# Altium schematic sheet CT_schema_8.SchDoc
size 278 x 170 mm
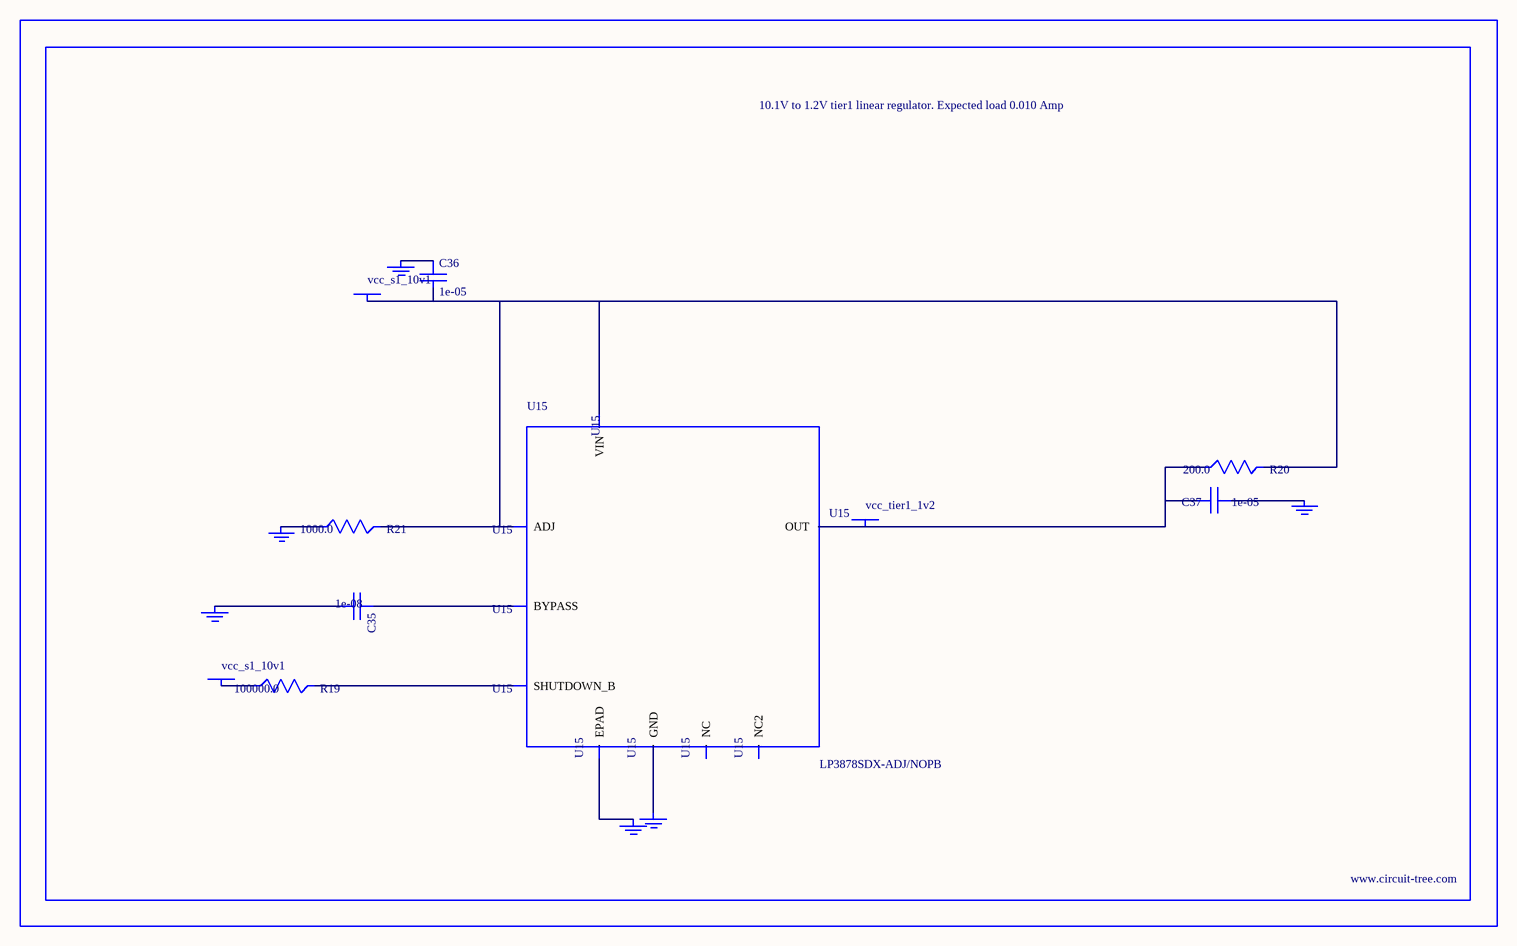
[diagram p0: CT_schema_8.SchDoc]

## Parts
BORDER7  (no value)
C35  1e-08  [C0402]
C36  1e-05  [C1206]
C37  1e-05  [C0805]
GND_INSTANCE_7_0  (no value)
GND_INSTANCE_7_1  (no value)
GND_INSTANCE_7_2  (no value)
GND_INSTANCE_7_3  (no value)
GND_INSTANCE_7_4  (no value)
GND_INSTANCE_7_5  (no value)
POWER_INSTANCE_7_0  vcc_s1_10v1
POWER_INSTANCE_7_1  vcc_s1_10v1
POWER_INSTANCE_7_2  vcc_tier1_1v2
R19  100000.0  [R0603]
R20  200.0  [R0603]
R21  1000.0  [R0603]
U15  LP3878SDX-ADJ/NOPB  [WSON-8]

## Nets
NetC35_1: C35.1 U15.1(BYPASS)
NetC35_2: C35.2 GND_INSTANCE_7_0.0(GND)
NetC36_1: C36.1 GND_INSTANCE_7_1.0(GND)
NetC36_2: C36.2 POWER_INSTANCE_7_0.0(PWR) R20.2 R21.2 U15.4(VIN) U15.6(ADJ)
NetC37_1: C37.1 GND_INSTANCE_7_2.0(GND)
NetC37_2: C37.2 POWER_INSTANCE_7_2.0(PWR) R20.1 U15.5(OUT)
NetGND_INSTANCE_7_3_0: GND_INSTANCE_7_3.0(GND) R21.1
NetGND_INSTANCE_7_4_0: GND_INSTANCE_7_4.0(GND) U15.PAD(EPAD)
NetGND_INSTANCE_7_5_0: GND_INSTANCE_7_5.0(GND) U15.3(GND)
NetPOWER_INSTANCE_7_1_0: POWER_INSTANCE_7_1.0(PWR) R19.1
NetR19_2: R19.2 U15.8(SHUTDOWN_B)

Not connected (* = marked no-connect by the designer): U15 2(NC) 7(NC2)

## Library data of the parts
BORDER7 = BORDER_PAGE7
C35 = C0402C103K3RAC
C36 = C1206C106K3RACTU
C37 = GRM219R60J106ME19D
GND_INSTANCE_7_0-GND_INSTANCE_7_5 = GND
POWER_INSTANCE_7_0-POWER_INSTANCE_7_2 = PWR
R19 = RC0603JR-07100KL
R20 = RC0603JR-07200RL
R21 = RC0603JR-071KL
